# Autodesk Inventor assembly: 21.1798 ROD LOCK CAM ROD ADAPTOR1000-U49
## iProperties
Created: 2007-03
Part Number: 21.1798 ROD LOCK CAM ROD ADAPTOR1000-U49
Document SubType Name: Assembly
Designer: Andy Moles
Translation Standard: STEP AP214IS
File Name: 1000-U49_ASM
Preprocessor: PRO/ENGINEER BY PARAMETRIC TECHNOLOGY CORPORATION, 2005310
Postprocessor: Build: 344b, Release: 11 SP2 - Date: Fri 08/18/2006
Sent Units: MILLIMETERS
Uncertainty: 0.004211719462213
Author: Andy Moles
